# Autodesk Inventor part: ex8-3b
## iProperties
Author: Administrator
Created: 2001-03
Part Number: ex8-3b
Document SubType Name: Modeling
Designer: Administrator
Control State: 0
Master: False
Checked Out: False
PropertySet Name: Design Tracking Control
Shininess: 20.0
PropertySet Name: _Private Model Information
Density: 0.0
Volumn: 0.0
Area: 0.0
PropertySet Name: Model Information
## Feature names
1. Extrusion1
2. Hole1
